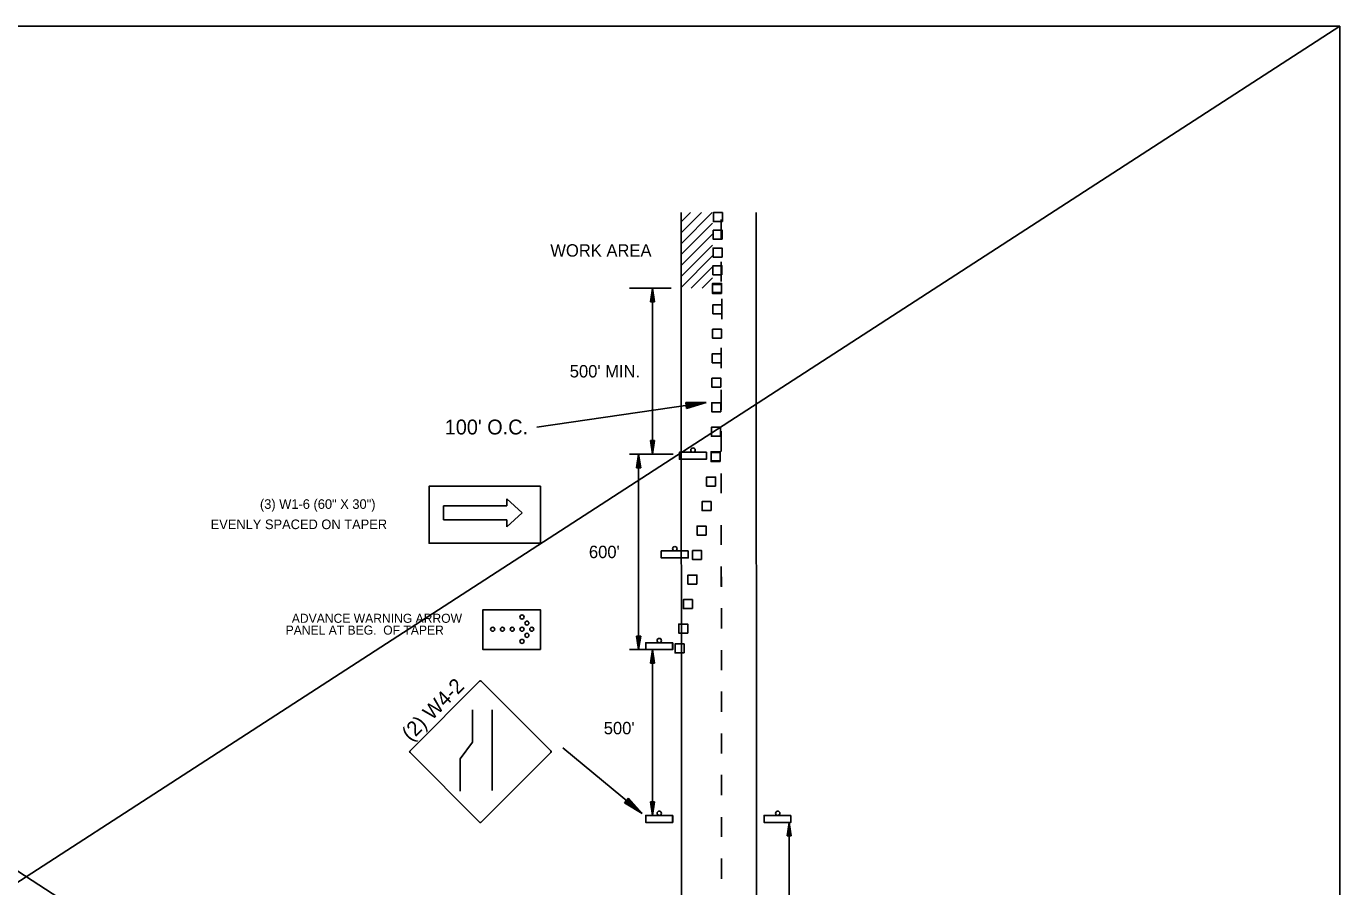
# Model space of a CAD drawing. Extents: x 1374027 to 1374537, y 380415 to 381405.
# Drawn here: x 1374452.1 to 1374537.1, y 381129.5 to 381185.2 of the extents above; entities that cross this region are included whole.
import ezdxf

# ---------------------------------------------------------------- set-up
doc = ezdxf.new("R2010")
doc.units = 0
for name, color, linetype in [('Default', 7, 'Continuous'), ('DSN_DRFT_Junk-No-Plot', 7, 'Continuous'), ('R_Exist Surface', 7, 'Continuous'), ('R_MOT', 7, 'Continuous')]:
    doc.layers.add(name, color=color, linetype=linetype)

msp = doc.modelspace()

# ---------------------------------------------------------------- linework, layer by layer
at = {"layer": 'Default'}
for p, q in [((1374494.467, 381172.529), (1374495.067, 381173.129)), ((1374494.468, 381171.114), (1374496.481, 381173.13)), ((1374494.468, 381171.822), (1374495.774, 381173.129)), ((1374494.468, 381170.407), (1374496.499, 381172.441)), ((1374494.469, 381169.7), (1374496.499, 381171.733)), ((1374494.469, 381168.993), (1374496.499, 381171.026)), ((1374494.47, 381168.286), (1374496.499, 381170.318)), ((1374495.116, 381168.226), (1374496.499, 381169.611)), ((1374495.823, 381168.226), (1374496.499, 381168.903))]:
    msp.add_line(p, q, dxfattribs=at)
msp.add_lwpolyline([(1374485.355, 381144.86), (1374481.631, 381144.86), (1374481.631, 381147.437), (1374485.355, 381147.437)], close=True, dxfattribs=at)
for centre in [(1374484.164, 381146.967), (1374482.267, 381146.178), (1374482.899, 381146.178), (1374483.532, 381146.178), (1374484.164, 381146.178), (1374484.48, 381146.572), (1374484.797, 381146.178), (1374484.164, 381145.389), (1374484.48, 381145.783)]:
    msp.add_circle(centre, 0.131, dxfattribs=at)
at = {"layer": 'DSN_DRFT_Junk-No-Plot'}
for p, q in [((1374367.083, 381075.174), (1374537.083, 381185.174)), ((1374367.083, 381185.174), (1374537.083, 381075.174))]:
    msp.add_line(p, q, dxfattribs=at)
for points in [[(1374367.083, 381185.174), (1374537.083, 381185.174), (1374537.083, 381075.174), (1374367.083, 381075.174)], [(1374367.083, 381185.174), (1374367.083, 381075.174), (1374537.083, 381075.174), (1374537.083, 381185.174)]]:
    msp.add_lwpolyline(points, close=True, dxfattribs=at)
at = {"layer": 'R_Exist Surface'}
for p, q in [((1374494.462, 381173.129), (1374494.502, 381104.039)), ((1374499.32, 381173.129), (1374499.361, 381104.042)), ((1374493.822, 381168.226), (1374491.123, 381168.226)), ((1374492.484, 381167.351), (1374492.615, 381168.226)), ((1374492.506, 381167.351), (1374492.615, 381168.08)), ((1374492.747, 381167.351), (1374492.615, 381168.226)), ((1374492.615, 381157.501), (1374492.615, 381168.226)), ((1374492.725, 381167.351), (1374492.615, 381168.08)), ((1374492.484, 381167.351), (1374492.747, 381167.351)), ((1374492.528, 381167.351), (1374492.615, 381167.929)), ((1374492.55, 381167.351), (1374492.615, 381167.784)), ((1374492.573, 381167.351), (1374492.615, 381167.635)), ((1374492.595, 381167.351), (1374492.615, 381167.489)), ((1374492.702, 381167.351), (1374492.615, 381167.929)), ((1374492.681, 381167.351), (1374492.615, 381167.784)), ((1374492.658, 381167.351), (1374492.615, 381167.635)), ((1374492.636, 381167.351), (1374492.615, 381167.489)), ((1374485.117, 381159.256), (1374496.084, 381160.842)), ((1374494.758, 381160.849), (1374496.084, 381160.842)), ((1374494.814, 381160.46), (1374494.758, 381160.849)), ((1374494.762, 381160.817), (1374495.867, 381160.811)), ((1374494.767, 381160.784), (1374495.644, 381160.779)), ((1374494.772, 381160.751), (1374495.428, 381160.747)), ((1374494.777, 381160.718), (1374495.208, 381160.716)), ((1374494.782, 381160.685), (1374494.991, 381160.684)), ((1374494.79, 381160.624), (1374494.991, 381160.684)), ((1374494.795, 381160.592), (1374495.208, 381160.716)), ((1374494.8, 381160.558), (1374495.428, 381160.747)), ((1374494.805, 381160.525), (1374495.644, 381160.779)), ((1374494.809, 381160.492), (1374495.867, 381160.811)), ((1374494.814, 381160.46), (1374496.084, 381160.842)), ((1374492.484, 381158.375), (1374492.615, 381157.501)), ((1374492.747, 381158.375), (1374492.484, 381158.375)), ((1374492.506, 381158.375), (1374492.615, 381157.647)), ((1374492.528, 381158.375), (1374492.615, 381157.797)), ((1374492.55, 381158.375), (1374492.615, 381157.943)), ((1374492.573, 381158.375), (1374492.615, 381158.091)), ((1374492.595, 381158.375), (1374492.615, 381158.237)), ((1374492.747, 381158.375), (1374492.615, 381157.501)), ((1374492.658, 381158.375), (1374492.615, 381158.091)), ((1374492.702, 381158.375), (1374492.615, 381157.797)), ((1374492.725, 381158.375), (1374492.615, 381157.647)), ((1374492.681, 381158.375), (1374492.615, 381157.943)), ((1374492.636, 381158.375), (1374492.615, 381158.237)), ((1374493.957, 381157.501), (1374491.123, 381157.501)), ((1374491.583, 381156.626), (1374491.714, 381157.501)), ((1374491.605, 381156.626), (1374491.714, 381157.355)), ((1374491.627, 381156.626), (1374491.714, 381157.204)), ((1374491.649, 381156.626), (1374491.714, 381157.059)), ((1374491.845, 381156.626), (1374491.714, 381157.501)), ((1374491.714, 381144.857), (1374491.714, 381157.501)), ((1374491.823, 381156.626), (1374491.714, 381157.355)), ((1374491.801, 381156.626), (1374491.714, 381157.204)), ((1374491.779, 381156.626), (1374491.714, 381157.059)), ((1374491.583, 381156.626), (1374491.845, 381156.626)), ((1374491.671, 381156.626), (1374491.714, 381156.91)), ((1374491.693, 381156.626), (1374491.714, 381156.764)), ((1374491.757, 381156.626), (1374491.714, 381156.91)), ((1374491.734, 381156.626), (1374491.714, 381156.764)), ((1374491.583, 381145.732), (1374491.714, 381144.857)), ((1374491.845, 381145.732), (1374491.583, 381145.732)), ((1374491.605, 381145.732), (1374491.714, 381145.003)), ((1374491.627, 381145.732), (1374491.714, 381145.154)), ((1374491.649, 381145.732), (1374491.714, 381145.299)), ((1374491.671, 381145.732), (1374491.714, 381145.448)), ((1374491.693, 381145.732), (1374491.714, 381145.594)), ((1374491.845, 381145.732), (1374491.714, 381144.857)), ((1374491.756, 381145.732), (1374491.714, 381145.448)), ((1374491.801, 381145.732), (1374491.714, 381145.154)), ((1374491.823, 381145.732), (1374491.714, 381145.003)), ((1374491.779, 381145.732), (1374491.714, 381145.299)), ((1374491.734, 381145.732), (1374491.714, 381145.594)), ((1374493.687, 381144.857), (1374491.123, 381144.857)), ((1374492.484, 381143.983), (1374492.615, 381144.857)), ((1374492.506, 381143.983), (1374492.615, 381144.711)), ((1374492.528, 381143.983), (1374492.615, 381144.561)), ((1374492.55, 381143.983), (1374492.615, 381144.416)), ((1374492.573, 381143.983), (1374492.615, 381144.267)), ((1374492.747, 381143.983), (1374492.615, 381144.857)), ((1374492.615, 381134.132), (1374492.615, 381144.857)), ((1374492.725, 381143.983), (1374492.615, 381144.711)), ((1374492.702, 381143.983), (1374492.615, 381144.561)), ((1374492.681, 381143.983), (1374492.615, 381144.416)), ((1374492.658, 381143.983), (1374492.615, 381144.267)), ((1374492.484, 381143.983), (1374492.747, 381143.983)), ((1374492.595, 381143.983), (1374492.615, 381144.121)), ((1374492.636, 381143.983), (1374492.615, 381144.121)), ((1374481.415, 381142.816), (1374476.917, 381138.316)), ((1374486.029, 381138.316), (1374481.531, 381142.816)), ((1374480.96, 381140.961), (1374480.96, 381138.867)), ((1374482.238, 381140.961), (1374482.238, 381135.74)), ((1374480.158, 381137.806), (1374480.96, 381138.867)), ((1374486.804, 381138.513), (1374491.933, 381134.261)), ((1374476.917, 381138.201), (1374481.415, 381133.702)), ((1374480.158, 381137.806), (1374480.158, 381135.713)), ((1374480.158, 381137.739), (1374480.158, 381137.806)), ((1374481.531, 381133.702), (1374486.029, 381138.201)), ((1374490.798, 381134.947), (1374491.049, 381135.25)), ((1374490.798, 381134.947), (1374491.933, 381134.261)), ((1374490.819, 381134.972), (1374491.765, 381134.401)), ((1374490.84, 381134.998), (1374491.591, 381134.545)), ((1374490.861, 381135.023), (1374491.423, 381134.684)), ((1374490.883, 381135.049), (1374491.252, 381134.826)), ((1374490.904, 381135.075), (1374491.083, 381134.966)), ((1374490.943, 381135.122), (1374491.083, 381134.966)), ((1374490.965, 381135.148), (1374491.252, 381134.826)), ((1374490.986, 381135.173), (1374491.423, 381134.684)), ((1374491.007, 381135.199), (1374491.591, 381134.545)), ((1374491.028, 381135.224), (1374491.765, 381134.401)), ((1374491.049, 381135.25), (1374491.933, 381134.261)), ((1374492.484, 381135.007), (1374492.615, 381134.132)), ((1374492.747, 381135.007), (1374492.484, 381135.007)), ((1374492.506, 381135.007), (1374492.615, 381134.278)), ((1374492.528, 381135.007), (1374492.615, 381134.429)), ((1374492.55, 381135.007), (1374492.615, 381134.574)), ((1374492.573, 381135.007), (1374492.615, 381134.723)), ((1374492.595, 381135.007), (1374492.615, 381134.869)), ((1374492.747, 381135.007), (1374492.615, 381134.132)), ((1374492.658, 381135.007), (1374492.615, 381134.723)), ((1374492.702, 381135.007), (1374492.615, 381134.429)), ((1374492.725, 381135.007), (1374492.615, 381134.278)), ((1374492.681, 381135.007), (1374492.615, 381134.574)), ((1374492.636, 381135.007), (1374492.615, 381134.869)), ((1374501.318, 381132.81), (1374501.449, 381133.684)), ((1374501.34, 381132.81), (1374501.449, 381133.538)), ((1374501.362, 381132.81), (1374501.449, 381133.388)), ((1374501.384, 381132.81), (1374501.449, 381133.242)), ((1374501.58, 381132.81), (1374501.449, 381133.684)), ((1374501.449, 381121.154), (1374501.449, 381133.684)), ((1374501.558, 381132.81), (1374501.449, 381133.538)), ((1374501.536, 381132.81), (1374501.449, 381133.388)), ((1374501.514, 381132.81), (1374501.449, 381133.242)), ((1374501.58, 381132.81), (1374501.318, 381132.81)), ((1374501.406, 381132.81), (1374501.449, 381133.094)), ((1374501.429, 381132.81), (1374501.449, 381132.948)), ((1374501.491, 381132.81), (1374501.449, 381133.094)), ((1374501.47, 381132.81), (1374501.449, 381132.948))]:
    msp.add_line(p, q, dxfattribs=at)
for points in [[(1374497.138, 381172.546), (1374496.555, 381172.546), (1374496.555, 381173.129), (1374497.138, 381173.129)], [(1374497.124, 381171.399), (1374496.541, 381171.399), (1374496.541, 381171.981), (1374497.124, 381171.981)], [(1374497.111, 381170.251), (1374496.528, 381170.251), (1374496.528, 381170.834), (1374497.111, 381170.834)], [(1374497.097, 381169.104), (1374496.514, 381169.104), (1374496.514, 381169.687), (1374497.097, 381169.687)], [(1374497.082, 381167.889), (1374496.499, 381167.889), (1374496.499, 381168.472), (1374497.082, 381168.472)], [(1374497.082, 381167.889), (1374496.499, 381167.889), (1374496.499, 381168.472), (1374497.082, 381168.472)], [(1374497.083, 381167.957), (1374496.501, 381167.957), (1374496.501, 381168.54), (1374497.083, 381168.54)], [(1374497.083, 381167.957), (1374496.501, 381167.957), (1374496.501, 381168.54), (1374497.083, 381168.54)], [(1374497.103, 381166.578), (1374496.52, 381166.578), (1374496.52, 381167.161), (1374497.103, 381167.161)], [(1374497.082, 381164.993), (1374496.499, 381164.993), (1374496.499, 381165.576), (1374497.082, 381165.576)], [(1374497.062, 381163.409), (1374496.479, 381163.409), (1374496.479, 381163.992), (1374497.062, 381163.992)], [(1374497.041, 381161.824), (1374496.459, 381161.824), (1374496.459, 381162.407), (1374497.041, 381162.407)], [(1374497.021, 381160.239), (1374496.439, 381160.239), (1374496.439, 381160.822), (1374497.021, 381160.822)], [(1374497.001, 381158.654), (1374496.418, 381158.654), (1374496.418, 381159.237), (1374497.001, 381159.237)], [(1374496.094, 381157.62), (1374494.354, 381157.62), (1374494.354, 381157.172), (1374496.094, 381157.172)], [(1374496.102, 381157.62), (1374494.354, 381157.62), (1374494.354, 381157.172), (1374496.102, 381157.172)], [(1374496.981, 381157.07), (1374496.398, 381157.07), (1374496.398, 381157.652), (1374496.981, 381157.652)], [(1374496.981, 381157.017), (1374496.398, 381157.017), (1374496.398, 381157.6), (1374496.981, 381157.6)], [(1374496.691, 381155.432), (1374496.109, 381155.432), (1374496.109, 381156.015), (1374496.691, 381156.015)], [(1374496.398, 381153.847), (1374495.815, 381153.847), (1374495.815, 381154.43), (1374496.398, 381154.43)], [(1374496.075, 381152.262), (1374495.493, 381152.262), (1374495.493, 381152.845), (1374496.075, 381152.845)], [(1374494.918, 381151.24), (1374493.178, 381151.24), (1374493.178, 381150.792), (1374494.918, 381150.792)], [(1374494.927, 381151.24), (1374493.178, 381151.24), (1374493.178, 381150.792), (1374494.927, 381150.792)], [(1374495.789, 381150.677), (1374495.207, 381150.677), (1374495.207, 381151.26), (1374495.789, 381151.26)], [(1374495.487, 381149.093), (1374494.904, 381149.093), (1374494.904, 381149.675), (1374495.487, 381149.675)], [(1374495.192, 381147.508), (1374494.609, 381147.508), (1374494.609, 381148.091), (1374495.192, 381148.091)], [(1374494.893, 381145.923), (1374494.31, 381145.923), (1374494.31, 381146.506), (1374494.893, 381146.506)], [(1374493.91, 381145.306), (1374492.17, 381145.306), (1374492.17, 381144.857), (1374493.91, 381144.857)], [(1374493.919, 381145.306), (1374492.17, 381145.306), (1374492.17, 381144.857), (1374493.919, 381144.857)], [(1374494.658, 381144.648), (1374494.075, 381144.648), (1374494.075, 381145.231), (1374494.658, 381145.231)], [(1374494.658, 381144.648), (1374494.075, 381144.648), (1374494.075, 381145.231), (1374494.658, 381145.231)], [(1374493.91, 381134.132), (1374492.17, 381134.132), (1374492.17, 381133.684), (1374493.91, 381133.684)], [(1374493.919, 381134.132), (1374492.17, 381134.132), (1374492.17, 381133.684), (1374493.919, 381133.684)], [(1374501.567, 381134.132), (1374499.827, 381134.132), (1374499.827, 381133.684), (1374501.567, 381133.684)], [(1374501.567, 381134.132), (1374499.827, 381134.132), (1374499.827, 381133.684), (1374501.567, 381133.684)], [(1374501.567, 381134.132), (1374499.827, 381134.132), (1374499.827, 381133.684), (1374501.567, 381133.684)], [(1374501.567, 381134.132), (1374499.827, 381134.132), (1374499.827, 381133.684), (1374501.567, 381133.684)]]:
    msp.add_lwpolyline(points, close=True, dxfattribs=at)
for points in [[(1374497.054, 381172.679), (1374497.055, 381171.364)], [(1374497.056, 381169.946), (1374497.057, 381168.664)], [(1374497.099, 381167.554), (1374497.099, 381166.238)], [(1374497.058, 381164.384), (1374497.059, 381163.069)], [(1374497.06, 381161.651), (1374497.06, 381160.369)], [(1374497.061, 381158.985), (1374497.062, 381157.669)], [(1374497.063, 381156.252), (1374497.063, 381154.969)], [(1374497.061, 381152.911), (1374497.062, 381151.629)], [(1374497.063, 381150.245), (1374497.064, 381148.93)], [(1374497.063, 381150.213), (1374497.063, 381148.931)], [(1374497.064, 381147.547), (1374497.065, 381146.231)], [(1374497.066, 381144.814), (1374497.067, 381143.531)], [(1374497.067, 381142.158), (1374497.068, 381140.842)], [(1374497.069, 381139.424), (1374497.07, 381138.142)], [(1374497.071, 381136.758), (1374497.071, 381135.443)], [(1374497.072, 381134.025), (1374497.073, 381132.743)], [(1374497.074, 381131.359), (1374497.074, 381130.043)]]:
    msp.add_lwpolyline(points, dxfattribs=at)
for centre in [(1374495.23, 381157.761), (1374494.054, 381151.381), (1374493.046, 381145.447), (1374493.046, 381134.273), (1374500.714, 381134.273)]:
    msp.add_ellipse(centre, major_axis=(0, 0.141), ratio=0.999914, dxfattribs=at)
for centre, major_axis, start_param, end_param in [((1374481.473, 381142.758), (0, 0.0816), 5.497787, 7.068583), ((1374476.974, 381138.259), (0, -0.0816), 3.926991, 5.497786), ((1374485.971, 381138.259), (0, 0.0816), 3.926992, 5.497787), ((1374481.473, 381133.76), (0, 0.0816), 2.356193, 3.926992)]:
    msp.add_ellipse(centre, major_axis=major_axis, ratio=0.999914, start_param=start_param, end_param=end_param, dxfattribs=at)
at = {"layer": 'R_MOT'}
for p, q in [((1374483.179, 381154.161), (1374483.179, 381154.618)), ((1374484.182, 381153.704), (1374483.179, 381154.618)), ((1374479.074, 381154.161), (1374483.179, 381154.161)), ((1374479.074, 381153.247), (1374479.074, 381154.161)), ((1374483.179, 381152.79), (1374484.182, 381153.704)), ((1374479.074, 381153.247), (1374483.179, 381153.247)), ((1374483.179, 381153.247), (1374483.179, 381152.79))]:
    msp.add_line(p, q, dxfattribs=at)
msp.add_lwpolyline([(1374485.355, 381151.743), (1374478.156, 381151.743), (1374478.156, 381155.424), (1374485.355, 381155.424)], close=True, dxfattribs=at)

# ---------------------------------------------------------------- texts
at = {"layer": 'Default'}
for s, p in [('ADVANCE WARNING ARROW', (1374469.267, 381146.592)), ('PANEL AT BEG.  OF TAPER', (1374468.867, 381145.828))]:
    msp.add_text(s, height=0.5862, dxfattribs=at).set_placement(p)
at = {"layer": 'R_Exist Surface'}
for s, height, p in [('WORK AREA', 0.8015, (1374485.996, 381170.276)), ("500' MIN.", 0.8015, (1374487.255, 381162.462)), ("100' O.C.", 0.9617, (1374479.164, 381158.775)), ("600'", 0.8015, (1374488.495, 381150.778)), ("500'", 0.8015, (1374489.454, 381139.383))]:
    msp.add_text(s, height=height, dxfattribs=at).set_placement(p)
msp.add_text('(2) W4-2', height=0.9617, rotation=45.00617, dxfattribs=at).set_placement((1374476.964, 381138.88))
at = {"layer": 'R_MOT'}
for s, p in [('(3) W1-6 (60" X 30")', (1374467.204, 381153.962)), ('EVENLY SPACED ON TAPER', (1374464.014, 381152.652))]:
    msp.add_text(s, height=0.6222, rotation=359.99246, dxfattribs=at).set_placement(p)

doc.saveas('drawing.dxf')
